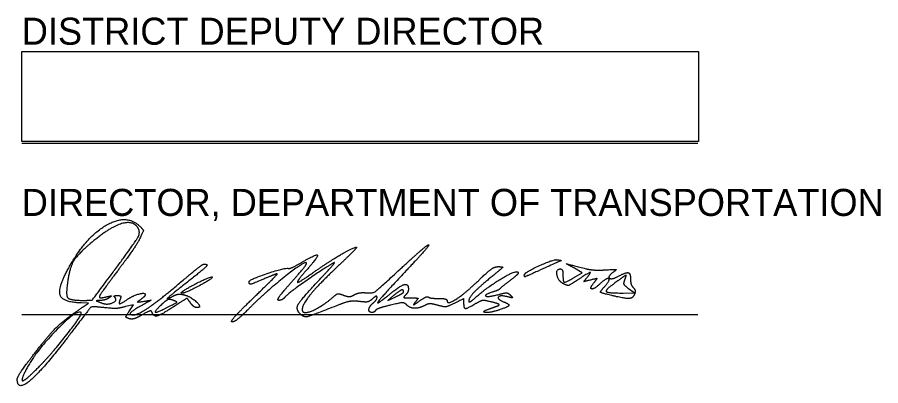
# Model space of a CAD drawing. Extents: x 0 to 40.2, y 0 to 22.
# Drawn here: x 35.681 to 40.151, y 5.889 to 7.796 of the extents above; entities that cross this region are included whole.
import ezdxf

# ---------------------------------------------------------------- set-up
doc = ezdxf.new("R2010")
doc.units = 0
doc.layers.add('GM_X_Adjacent_County', color=7, linetype='Continuous')
doc.layers.add('GM_X_Adjacent_County_Text', color=7, linetype='Continuous')

msp = doc.modelspace()

# ---------------------------------------------------------------- linework, layer by layer
at = {"layer": 'GM_X_Adjacent_County'}
for p, q in [((35.7046, 7.1435), (39.2046, 7.1435)), ((35.7046, 6.2575), (39.2046, 6.2575))]:
    msp.add_line(p, q, dxfattribs=at)
msp.add_lwpolyline([(35.7046, 7.1535), (35.7046, 7.6183), (39.2087, 7.6183), (39.2087, 7.1535)], close=True, dxfattribs=at)
at = {"layer": 'GM_X_Adjacent_County_Text'}
for p, q in [((36.1669, 6.4625), (36.1669, 6.4625)), ((38.3062, 6.4617), (38.3062, 6.4617)), ((36.5323, 6.3727), (36.5323, 6.3727)), ((37.6812, 6.3747), (37.6812, 6.3747)), ((38.7587, 6.3555), (38.7587, 6.3555)), ((36.4875, 6.331), (36.4875, 6.331)), ((36.9041, 6.3437), (36.9041, 6.3437))]:
    msp.add_line(p, q, dxfattribs=at)
for points in [[(38.57, 6.4521), (38.6064, 6.4736), (38.5657, 6.4966)], [(37.6295, 6.355), (37.6, 6.3294), (37.6406, 6.3491)], [(38.8187, 6.3686), (38.875, 6.3687), (38.8462, 6.3908)], [(36.0193, 6.2956), (36.05, 6.3168), (36.0121, 6.3175)], [(36.2622, 6.2757), (36.2834, 6.3081), (36.2417, 6.298)]]:
    msp.add_lwpolyline(points, dxfattribs=at)
for points in [[(35.9556, 6.5133), (36.0419, 6.6637), (36.25, 6.7797), (36.3157, 6.714)], [(36.3067, 6.7049), (36.2807, 6.7469), (36.1546, 6.7057), (36.0593, 6.6241)], [(36.3157, 6.714), (36.3344, 6.6953), (36.3345, 6.6902), (36.3161, 6.6518)], [(36.1669, 6.4625), (36.2883, 6.626), (36.3207, 6.6822), (36.3067, 6.7049)], [(36.0593, 6.6241), (35.9926, 6.5671), (35.9538, 6.503), (35.9427, 6.4317)], [(36.3161, 6.6518), (36.3052, 6.6288), (36.2535, 6.5533), (36.2012, 6.4839)], [(37.6636, 6.4922), (37.7386, 6.5613), (37.8047, 6.6179), (37.8104, 6.618)], [(37.8104, 6.618), (37.8161, 6.6181), (37.7641, 6.5579), (37.6948, 6.4843)], [(37.2093, 6.4718), (37.2899, 6.5284), (37.4212, 6.6056), (37.4369, 6.6056)], [(37.4369, 6.6056), (37.4418, 6.6056), (37.4005, 6.563), (37.3451, 6.5109)], [(37.1504, 6.5253), (37.2291, 6.5714), (37.2414, 6.5582), (37.1821, 6.4909)], [(38.3062, 6.4617), (38.3062, 6.4741), (38.4591, 6.5444), (38.478, 6.5407)], [(38.478, 6.5407), (38.4986, 6.5367), (38.4994, 6.5371), (38.3778, 6.4825)], [(36.0121, 6.3175), (35.9142, 6.3192), (35.8908, 6.4003), (35.9556, 6.5133)], [(36.2012, 6.4839), (36.149, 6.4145), (36.1062, 6.3539), (36.1062, 6.3491)], [(36.5457, 6.4398), (36.5962, 6.4827), (36.6417, 6.5178), (36.6468, 6.5179)], [(36.6468, 6.5179), (36.6717, 6.5184), (36.6483, 6.4929), (36.5625, 6.4256)], [(37.1785, 6.525), (37.1689, 6.5347), (36.9591, 6.3677), (36.8812, 6.2884)], [(36.8814, 6.4275), (36.8816, 6.438), (37.069, 6.5012), (37.0848, 6.4961)], [(37.3187, 6.5246), (37.2697, 6.4968), (37.0813, 6.3646), (37.0681, 6.3486)], [(37.0848, 6.4961), (37.0903, 6.4942), (37.1198, 6.5074), (37.1504, 6.5253)], [(37.1006, 6.4247), (37.1469, 6.4764), (37.182, 6.5216), (37.1785, 6.525)], [(37.1821, 6.4909), (37.1541, 6.4591), (37.1312, 6.4294), (37.1312, 6.425)], [(37.3451, 6.5109), (37.2455, 6.4172), (37.1562, 6.3091), (37.1562, 6.2821)], [(37.2535, 6.4457), (37.2997, 6.4949), (37.329, 6.5304), (37.3187, 6.5246)], [(37.4886, 6.3698), (37.5221, 6.367), (37.5456, 6.3834), (37.6636, 6.4922)], [(37.6948, 6.4843), (37.5652, 6.3468), (37.5331, 6.2995), (37.6153, 6.3672)], [(38.0719, 6.4359), (38.117, 6.4797), (38.1542, 6.5054), (38.1719, 6.5051)], [(38.1719, 6.5051), (38.1962, 6.5046), (38.1924, 6.4982), (38.1437, 6.4582)], [(38.3778, 6.4825), (38.3152, 6.4544), (38.3062, 6.4517), (38.3062, 6.4617)], [(38.5072, 6.4176), (38.4808, 6.4318), (38.4698, 6.4931), (38.4937, 6.4931)], [(38.4937, 6.4931), (38.5006, 6.4931), (38.5062, 6.4791), (38.5062, 6.4619)], [(38.5657, 6.4966), (38.5229, 6.5207), (38.5219, 6.5207), (38.625, 6.4943)], [(38.625, 6.4943), (38.6456, 6.4891), (38.6906, 6.4863), (38.725, 6.4882)], [(38.725, 6.4882), (38.7798, 6.4913), (38.7847, 6.4897), (38.7648, 6.4749)], [(36.0208, 6.3306), (36.0675, 6.3306), (36.072, 6.3347), (36.1669, 6.4625)], [(36.2844, 6.2556), (36.3075, 6.2556), (36.4335, 6.3444), (36.5457, 6.4398)], [(36.5323, 6.3727), (36.5527, 6.3905), (36.6847, 6.4563), (36.6898, 6.4512)], [(36.6898, 6.4512), (36.696, 6.445), (36.5534, 6.3681), (36.5357, 6.3681)], [(36.9625, 6.4431), (36.8999, 6.4163), (36.8811, 6.4127), (36.8814, 6.4275)], [(36.9041, 6.3437), (36.9751, 6.4121), (37.0304, 6.4681), (37.027, 6.4681)], [(37.027, 6.4681), (37.0236, 6.4681), (36.9945, 6.4569), (36.9625, 6.4431)], [(37.1465, 6.26), (37.1213, 6.2852), (37.1502, 6.3354), (37.2535, 6.4457)], [(37.1312, 6.425), (37.1312, 6.4205), (37.1664, 6.4416), (37.2093, 6.4718)], [(38.1437, 6.4582), (38.0697, 6.3972), (38.0187, 6.3437), (38.0187, 6.327)], [(38.0531, 6.3448), (38.1067, 6.3936), (38.2537, 6.4836), (38.2706, 6.4779)], [(38.2706, 6.4779), (38.2789, 6.4751), (38.2637, 6.4564), (38.2366, 6.4362)], [(38.5062, 6.4619), (38.5062, 6.4251), (38.5205, 6.4229), (38.57, 6.4521)], [(38.6296, 6.4473), (38.654, 6.4769), (38.6382, 6.4731), (38.582, 6.4359)], [(38.649, 6.4356), (38.616, 6.4274), (38.6141, 6.4285), (38.6296, 6.4473)], [(38.6691, 6.4249), (38.6837, 6.4425), (38.6814, 6.4437), (38.649, 6.4356)], [(38.723, 6.4034), (38.7535, 6.4371), (38.7318, 6.448), (38.6978, 6.4161)], [(38.7648, 6.4749), (38.736, 6.4534), (38.759, 6.437), (38.7926, 6.4551)], [(38.8265, 6.4363), (38.8364, 6.4621), (38.8282, 6.459), (38.7656, 6.4134)], [(38.7926, 6.4551), (38.8329, 6.4766), (38.8562, 6.4708), (38.8562, 6.4394)], [(38.8562, 6.4394), (38.8562, 6.4236), (38.8626, 6.4043), (38.8704, 6.3965)], [(35.9427, 6.4317), (35.9313, 6.3583), (35.9527, 6.3306), (36.0208, 6.3306)], [(36.5625, 6.4256), (36.4693, 6.3526), (36.4478, 6.331), (36.4917, 6.3545)], [(37.0348, 6.3306), (37.0245, 6.3306), (37.0534, 6.3719), (37.1006, 6.4247)], [(37.6153, 6.3672), (37.6637, 6.4071), (37.7062, 6.4175), (37.7062, 6.3894)], [(37.9062, 6.3291), (37.9062, 6.3063), (38.0015, 6.3677), (38.0719, 6.4359)], [(38.2366, 6.4362), (38.2096, 6.416), (38.1847, 6.396), (38.1812, 6.3918)], [(38.582, 6.4359), (38.5419, 6.4094), (38.5286, 6.4061), (38.5072, 6.4176)], [(38.6978, 6.4161), (38.6659, 6.3861), (38.6428, 6.3932), (38.6691, 6.4249)], [(38.7587, 6.3555), (38.704, 6.3684), (38.6983, 6.3761), (38.723, 6.4034)], [(38.7656, 6.4134), (38.7229, 6.3823), (38.7393, 6.3685), (38.8187, 6.3686)], [(38.8462, 6.3908), (38.8259, 6.4065), (38.8201, 6.4197), (38.8265, 6.4363)], [(38.8704, 6.3965), (38.8782, 6.3887), (38.8812, 6.3735), (38.877, 6.3627)], [(36.1062, 6.3491), (36.1062, 6.3443), (36.1217, 6.344), (36.1406, 6.3484)], [(36.1406, 6.3484), (36.1661, 6.3543), (36.1701, 6.3531), (36.1562, 6.3437)], [(36.1853, 6.3474), (36.1808, 6.3519), (36.187, 6.3556), (36.1992, 6.3556)], [(36.1992, 6.3556), (36.2138, 6.3556), (36.2189, 6.3492), (36.2142, 6.3369)], [(36.2503, 6.335), (36.2792, 6.3548), (36.3437, 6.3723), (36.3437, 6.3604)], [(36.3437, 6.3604), (36.3437, 6.3558), (36.334, 6.345), (36.3221, 6.3363)], [(36.4917, 6.3545), (36.5043, 6.3613), (36.5282, 6.3634), (36.5448, 6.3592)], [(36.5357, 6.3681), (36.531, 6.3681), (36.5294, 6.3702), (36.5323, 6.3727)], [(36.5448, 6.3592), (36.5809, 6.3501), (36.6393, 6.2931), (36.6126, 6.2931)], [(37.0681, 6.3486), (37.0599, 6.3387), (37.0449, 6.3306), (37.0348, 6.3306)], [(37.3137, 6.3456), (37.334, 6.3637), (37.3469, 6.3663), (37.3706, 6.3573)], [(37.3706, 6.3573), (37.3908, 6.3496), (37.4096, 6.3503), (37.4256, 6.3593)], [(37.4256, 6.3593), (37.439, 6.3669), (37.4674, 6.3716), (37.4886, 6.3698)], [(37.5437, 6.3466), (37.5437, 6.3537), (37.5336, 6.3503), (37.5211, 6.3391)], [(37.6812, 6.3747), (37.6812, 6.3882), (37.6571, 6.379), (37.6295, 6.355)], [(37.6406, 6.3491), (37.6629, 6.3599), (37.6812, 6.3714), (37.6812, 6.3747)], [(37.6912, 6.3581), (37.6796, 6.3465), (37.6854, 6.3431), (37.7177, 6.3431)], [(37.7062, 6.3894), (37.7062, 6.3804), (37.6995, 6.3664), (37.6912, 6.3581)], [(37.7639, 6.3276), (37.7853, 6.3426), (37.806, 6.3517), (37.8099, 6.3478)], [(37.8099, 6.3478), (37.8138, 6.3438), (37.8371, 6.3406), (37.8616, 6.3406)], [(38.1468, 6.3752), (38.0973, 6.3598), (38.1168, 6.3461), (38.1687, 6.3599)], [(38.1812, 6.3918), (38.1778, 6.3875), (38.1623, 6.38), (38.1468, 6.3752)], [(38.1687, 6.3599), (38.207, 6.3702), (38.2222, 6.3696), (38.2343, 6.3573)], [(38.2156, 6.3498), (38.1789, 6.3589), (38.1656, 6.3358), (38.2, 6.3226)], [(38.2343, 6.3573), (38.247, 6.3444), (38.2434, 6.343), (38.2156, 6.3498)], [(38.877, 6.3627), (38.8689, 6.3416), (38.8278, 6.3391), (38.7587, 6.3555)], [(36.1125, 6.33), (36.0901, 6.3291), (36.0905, 6.3278), (36.1166, 6.3174)], [(36.1562, 6.3437), (36.1459, 6.3367), (36.1262, 6.3306), (36.1125, 6.33)], [(36.1166, 6.3174), (36.1465, 6.3054), (36.2027, 6.3299), (36.1853, 6.3474)], [(36.2142, 6.3369), (36.2053, 6.3136), (36.2181, 6.313), (36.2503, 6.335)], [(36.3289, 6.3063), (36.2778, 6.2781), (36.2581, 6.2556), (36.2844, 6.2556)], [(36.3221, 6.3363), (36.3032, 6.3225), (36.3052, 6.3212), (36.3377, 6.3261)], [(36.3377, 6.3261), (36.3745, 6.3317), (36.3744, 6.3314), (36.3289, 6.3063)], [(36.4343, 6.3145), (36.3901, 6.274), (36.4013, 6.2651), (36.4593, 6.2947)], [(36.4875, 6.331), (36.4702, 6.3374), (36.4537, 6.3322), (36.4343, 6.3145)], [(36.4593, 6.2947), (36.5057, 6.3184), (36.5093, 6.323), (36.4875, 6.331)], [(36.5779, 6.3178), (36.561, 6.3419), (36.559, 6.3414), (36.4932, 6.299)], [(36.6126, 6.2931), (36.603, 6.2931), (36.5874, 6.3042), (36.5779, 6.3178)], [(36.7937, 6.2188), (36.7834, 6.219), (36.8331, 6.2752), (36.9041, 6.3437)], [(37.3461, 6.3075), (37.2, 6.2498), (37.165, 6.2415), (37.1465, 6.26)], [(37.1743, 6.2681), (37.196, 6.2681), (37.2773, 6.3133), (37.3137, 6.3456)], [(37.4516, 6.3247), (37.4224, 6.3284), (37.3826, 6.3219), (37.3461, 6.3075)], [(37.5211, 6.3391), (37.5055, 6.3249), (37.4842, 6.3205), (37.4516, 6.3247)], [(37.518, 6.2681), (37.4996, 6.2681), (37.5042, 6.3009), (37.525, 6.3181)], [(37.525, 6.3181), (37.5353, 6.3267), (37.5437, 6.3395), (37.5437, 6.3466)], [(37.6123, 6.3056), (37.5739, 6.2964), (37.5397, 6.2842), (37.5361, 6.2785)], [(37.6966, 6.3077), (37.6855, 6.3188), (37.6655, 6.3183), (37.6123, 6.3056)], [(37.7929, 6.3052), (37.7622, 6.2888), (37.7143, 6.29), (37.6966, 6.3077)], [(37.7177, 6.3431), (37.7553, 6.3431), (37.7576, 6.3411), (37.7421, 6.3217)], [(37.7421, 6.3217), (37.7301, 6.3067), (37.7366, 6.3085), (37.7639, 6.3276)], [(37.8574, 6.3053), (37.8305, 6.313), (37.8074, 6.313), (37.7929, 6.3052)], [(37.9465, 6.3166), (37.9091, 6.2981), (37.8906, 6.2958), (37.8574, 6.3053)], [(37.8616, 6.3406), (37.8862, 6.3406), (37.9062, 6.3355), (37.9062, 6.3291)], [(37.9937, 6.3166), (37.9937, 6.3395), (37.9926, 6.3395), (37.9465, 6.3166)], [(38.0557, 6.3135), (38.0106, 6.2869), (37.9937, 6.2878), (37.9937, 6.3166)], [(38.0187, 6.327), (38.0187, 6.3195), (38.0342, 6.3275), (38.0531, 6.3448)], [(38.1388, 6.3216), (38.1, 6.3314), (38.0832, 6.3298), (38.0557, 6.3135)], [(38.1687, 6.3023), (38.1801, 6.3065), (38.1684, 6.314), (38.1388, 6.3216)], [(38.2, 6.3226), (38.2305, 6.3109), (38.2216, 6.296), (38.1749, 6.2806)], [(36.0121, 6.2664), (35.9912, 6.2873), (35.7727, 6.0616), (35.7264, 5.9713)], [(35.7684, 6.0534), (35.846, 6.1539), (35.9261, 6.2312), (36.0193, 6.2956)], [(35.7965, 5.99), (35.8641, 6.0591), (36.0198, 6.2587), (36.0121, 6.2664)], [(36.1005, 6.2957), (36.0671, 6.299), (36.0553, 6.2885), (35.9787, 6.1869)], [(36.2417, 6.298), (36.2013, 6.2883), (36.179, 6.2879), (36.1005, 6.2957)], [(36.261, 6.2357), (36.2428, 6.2427), (36.2429, 6.2463), (36.2622, 6.2757)], [(36.3787, 6.2693), (36.3759, 6.2779), (36.3567, 6.2727), (36.3276, 6.2555)], [(36.4932, 6.299), (36.4243, 6.2547), (36.3869, 6.245), (36.3787, 6.2693)], [(36.8812, 6.2884), (36.8434, 6.25), (36.804, 6.2186), (36.7937, 6.2188)], [(37.1562, 6.2821), (37.1562, 6.2744), (37.1643, 6.2681), (37.1743, 6.2681)], [(37.5361, 6.2785), (37.5326, 6.2728), (37.5245, 6.2681), (37.518, 6.2681)], [(38.1749, 6.2806), (38.1283, 6.2652), (38.0809, 6.2709), (38.125, 6.2866)], [(38.125, 6.2866), (38.1387, 6.2915), (38.1584, 6.2986), (38.1687, 6.3023)], [(36.3276, 6.2555), (36.302, 6.2404), (36.272, 6.2315), (36.261, 6.2357)], [(35.9787, 6.1869), (35.8263, 5.9848), (35.6812, 5.8562), (35.6812, 5.9232)], [(35.6812, 5.9232), (35.6812, 5.9328), (35.7204, 5.9914), (35.7684, 6.0534)], [(35.7264, 5.9713), (35.6952, 5.9103), (35.7268, 5.9188), (35.7965, 5.99)]]:
    msp.add_open_spline(points, degree=2, dxfattribs=at)

# ---------------------------------------------------------------- texts
for s, p in [('DISTRICT DEPUTY DIRECTOR', (35.7046, 7.6535)), ('DIRECTOR, DEPARTMENT OF TRANSPORTATION', (35.7046, 6.7675))]:
    msp.add_text(s, height=0.14, dxfattribs=at).set_placement(p)

doc.saveas('drawing.dxf')
